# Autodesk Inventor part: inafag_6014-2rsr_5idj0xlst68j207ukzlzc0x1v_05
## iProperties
Shininess: 64.0
Angle Display Precision: 2
Document Length Units: 11269
Document Angle Units: 11279
Document Time Units: 11290
Document Mass Units: 11283
Document Length Units Precision: 3
Document Angle Units Precision: 2
Compacted: True
Created: 2008-08
Part Number: inafag_6014-2rsr_5idj0xlst68j207ukzlzc0x1v_05
Document SubType Name: Modeling
Designer: tpomodeler
Density: 0.0
Volumn: 0.0
Area: 0.0
PropertySet Name: Model Information
Control State: 0
Master: False
Checked Out: False
Author: tpomodeler
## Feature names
1. inafag_6014-2rsr_5idj0xlst68j207ukzlzc0x1v
